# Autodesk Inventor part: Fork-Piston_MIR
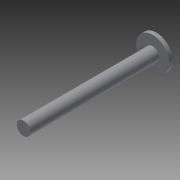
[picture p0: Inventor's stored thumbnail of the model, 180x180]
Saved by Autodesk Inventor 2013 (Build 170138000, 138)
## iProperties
Created: 2001-11
Part Number: Fork-Piston_MIR
Document SubType Name: Modeling
Designer: Autodesk, Inc.
Mass: 6.28409 g
Surface Area: 33.2778 cm^2
Volume: 6.28409 cm^3
Density: 1 g/cm^3
Material: Generic
Author: Autodesk, Inc.
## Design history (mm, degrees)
derived "Fork-Piston.ipt"
body "Solid1"
tag "TaggingFeature2"
feature "DerivedBody::Fork-Piston.ipt" dims "d0" = 10
